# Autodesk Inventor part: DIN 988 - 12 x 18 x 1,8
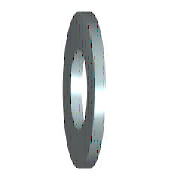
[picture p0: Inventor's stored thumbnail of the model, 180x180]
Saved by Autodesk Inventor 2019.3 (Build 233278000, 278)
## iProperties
Created: 2018-01
Part Number: DIN 988 - 12 x 18 x 1,8
Material: Ocel, měkká
Description: Vyrovnávací kroužek
Document SubType Name: Modeling
Standard: DIN 988
Designer: B-hon
Standard Revision: 1990
Standards Organization: DIN
Language: cs-CZ
Size Designation: 12 x 18 x 1,8
Categories: <MemberInstance><Categories><Category DisplayName="Součásti hřídele" InternalName="7f7aeb1f-a693-4053-b835-cee3144e0d98" Mnemonic="SHFT"><Category DisplayName="
Density: 7.85 g/cm^3
Appearance: Pololeštěná
IsCustomPart: 0
Author: B-hon
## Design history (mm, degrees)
sketch "Náčrt1"
  geometry: L1 (-21, 0)-(21, 0) reference; L2 (0, 21)-(0, -21) reference; C1 r 6 at (0, 0); C2 r 9 at (0, 0)
  constraints: 2 centre point, 2 midpoint, 1 coincident, 1 other
  dimensions: "d0" = 12 diameter of C1 (= SD1); "d1" = 18 diameter of C2 (= SD2)
extrude "Těleso" new body sketch "Náčrt1" distance "d2" = 1.8 (= SD); taper "d3" = 0 deg
body "Solid1"
other parameters: "SD2" = 18 [user parameter; used in 1 equation term], "SD" = 1.8 [user parameter; used in 1 equation term], "SD1" = 12 [user parameter; used in 1 equation term], "d4" = 0, "d5" = 0, "NND" = 12 [user parameter], "SR" = 9 (= 0.5 x NND2) [user parameter], "NND2" = 18 [user parameter; used in 1 equation term]
